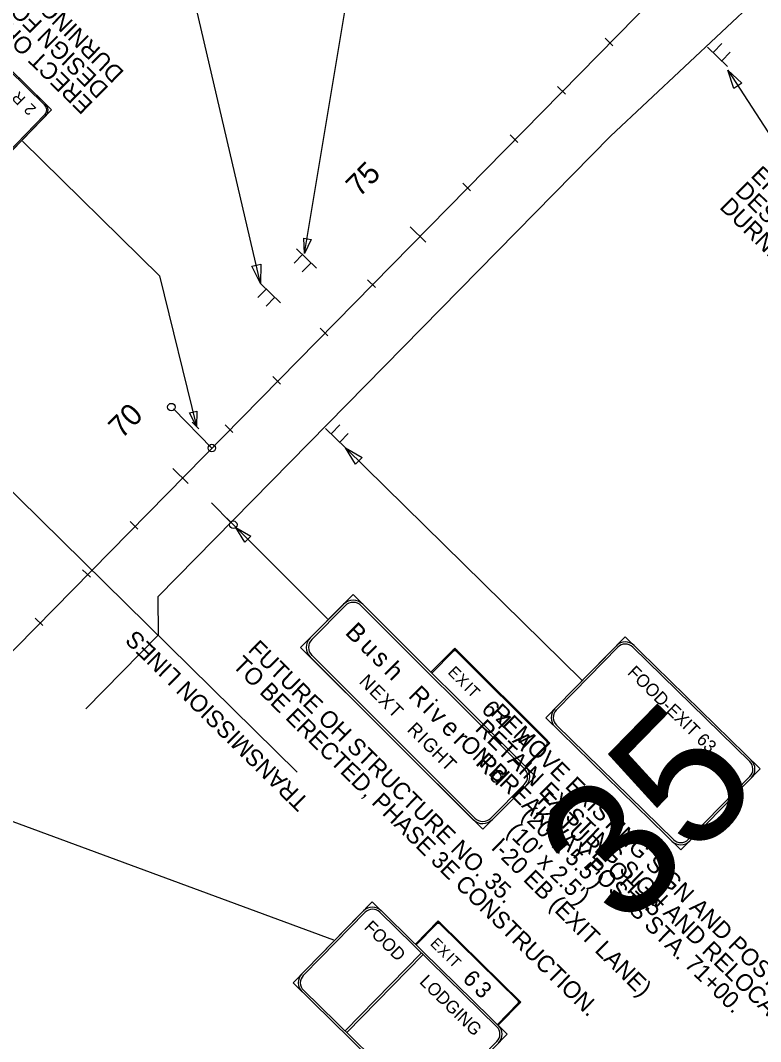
# Model space of a CAD drawing. Extents: x -5665 to 1997148, y 4 to 812485.
# Drawn here: x 1959336 to 1960429, y 795278 to 796785 of the extents above; entities that cross this region are included whole.
import ezdxf

# ---------------------------------------------------------------- set-up
doc = ezdxf.new("R2010")
doc.units = 0
for name, color, linetype in [('Default', 7, 'Continuous'), ('RD_HC_CL_Rel', 7, 'Continuous'), ('RD_HC_Data_Tic_Rel', 7, 'Continuous'), ('RD_HC_TX_Rel_Sta50', 7, 'Continuous'), ('RD_PD_Final_TX', 7, 'Continuous'), ('RD_SHT_TX', 7, 'Continuous'), ('TR SN EXTRUDED PANEL SIGNS- MOUNTED OVERHEAD', 7, 'Continuous'), ('TR SN UNASSIGNED 10', 7, 'Continuous')]:
    doc.layers.add(name, color=color, linetype=linetype)

msp = doc.modelspace()

# ---------------------------------------------------------------- linework, layer by layer
at = {"layer": 'Default'}
for p, q in [((1960207.3, 796614.2), (1960426.3, 796819.7)), ((1959539.4, 795935.2), (1960207.3, 796614.2)), ((1959539.9, 795878.6), (1959539.4, 795935.2)), ((1959432.5, 795769.5), (1959539.9, 795878.6))]:
    msp.add_line(p, q, dxfattribs=at)
at = {"layer": 'RD_HC_CL_Rel'}
msp.add_line((1957622, 794124.4), (1963740.1, 800343.8), dxfattribs=at)
at = {"layer": 'RD_HC_Data_Tic_Rel'}
for p, q in [((1960210.9, 796747.6), (1960199.5, 796758.8)), ((1960140.7, 796676.3), (1960129.3, 796687.5)), ((1960070.6, 796605), (1960059.2, 796616.2)), ((1960000.5, 796533.7), (1959989.1, 796544.9)), ((1959934.6, 796458.2), (1959911.8, 796480.6)), ((1959860.2, 796391.1), (1959848.8, 796402.3)), ((1959790.1, 796319.8), (1959778.7, 796331)), ((1959720, 796248.5), (1959708.6, 796259.8)), ((1959649.8, 796177.2), (1959638.4, 796188.5)), ((1959584, 796101.7), (1959561.2, 796124.2)), ((1959509.6, 796034.7), (1959498.2, 796045.9)), ((1959439.5, 795963.4), (1959428, 795974.6)), ((1959369.3, 795892.1), (1959357.9, 795903.3))]:
    msp.add_line(p, q, dxfattribs=at)
at = {"layer": 'RD_PD_Final_TX'}
for points in [[(1960401.3, 796692.4), (1960389.7, 796684.9), (1960380.5, 796711.8)], [(1959677.8, 796422.5), (1959691.2, 796425.6), (1959690.8, 796397.2)], [(1959840.7, 796140.1), (1959831.1, 796130.3), (1959816.3, 796154.5)]]:
    msp.add_lwpolyline(points, close=True, dxfattribs=at)
at = {"layer": 'RD_SHT_TX'}
msp.add_line((1959283.6, 796129.4), (1959744.5, 795676), dxfattribs=at)
at = {"layer": 'TR SN EXTRUDED PANEL SIGNS- MOUNTED OVERHEAD'}
for p, q in [((1959755.5, 796441.3), (1959875.4, 797157.2)), ((1959690.8, 796397.2), (1959583.5, 796857.2)), ((1960350.6, 796745.7), (1960380.1, 796717.2)), ((1960371.7, 796751), (1960359.3, 796738.2)), ((1960383.9, 796738.3), (1960371.6, 796725.5)), ((1960380.5, 796711.8), (1960650.1, 796295.2)), ((1959541.4, 796408.1), (1959339.4, 796606.8)), ((1959740.1, 796427.1), (1959752.5, 796439.9)), ((1959773.5, 796419.6), (1959744, 796448.2)), ((1959752.3, 796414.4), (1959764.7, 796427.2)), ((1959541.4, 796408.1), (1959596, 796185.9)), ((1959720.3, 796368.7), (1959690.8, 796397.2)), ((1959686.9, 796376.1), (1959699.3, 796388.9)), ((1959699.1, 796363.4), (1959711.5, 796376.2)), ((1959618.7, 796154.2), (1959562.1, 796212)), ((1959599.5, 796182.3), (1959589.7, 796192.3)), ((1959786.7, 796183.1), (1959816.3, 796154.5)), ((1959807.9, 796188.3), (1959795.5, 796175.5)), ((1959820.1, 796175.6), (1959807.7, 796162.8)), ((1959816.3, 796154.5), (1960165, 795811.5)), ((1959275.7, 795621.4), (1959798.6, 795428.3))]:
    msp.add_line(p, q, dxfattribs=at)
for points in [[(1959382.1, 796653.2), (1959257, 796775.5), (1959169.6, 796686.2), (1959294.7, 796563.8), (1959382.1, 796653.2), (1959382.1, 796653.2), (1959382.1, 796653.2)], [(1959371.7, 796660.4), (1959264.5, 796765.3)], [(1959266, 796766.8), (1959373.2, 796661.9)], [(1959371.7, 796660.4), (1959371.7, 796660.4), (1959371.7, 796660.4)], [(1959302, 796574.2), (1959371.9, 796645.7)], [(1959373.4, 796644.2), (1959303.5, 796572.8)], [(1960350.4, 795601), (1960428.4, 795680.7), (1960229, 795875.7), (1960151, 795795.9), (1960151, 795795.9)], [(1960151, 795795.9), (1960216, 795862.4)], [(1960218.2, 795860.2), (1960153.3, 795793.8)], [(1960412.9, 795691.5), (1960240.1, 795860.5)], [(1960151, 795795.9), (1960112.1, 795756.1), (1960112.1, 795756.1)], [(1960153.3, 795793.8), (1960127.3, 795767.2)], [(1960112.1, 795756.1), (1960311.4, 795561.1), (1960350.4, 795601)], [(1960127.5, 795745.3), (1960300.3, 795576.3)], [(1960348.2, 795603.2), (1960413.1, 795669.6)], [(1960322.2, 795576.6), (1960348.2, 795603.2)], [(1959976.9, 795209.7), (1960054.9, 795289.5), (1959855.6, 795484.4), (1959777.6, 795404.7), (1959777.6, 795404.7)], [(1959777.6, 795404.7), (1959842.6, 795471.1)], [(1959844.8, 795468.9), (1959779.8, 795402.5)], [(1960039.5, 795300.2), (1959866.7, 795469.2)], [(1959954.3, 795454.9), (1959952.9, 795456.4), (1959919.3, 795422.1), (1959919.3, 795422.1)], [(1959950.7, 795451.8), (1959920.5, 795421)], [(1960070.6, 795339), (1959955.2, 795451.9)], [(1960041.6, 795302.5), (1960075.1, 795336.7), (1959956.3, 795453)], [(1959777.6, 795404.7), (1959738.6, 795364.8), (1959738.6, 795364.8)], [(1959779.8, 795402.5), (1959753.8, 795375.9)], [(1959815.4, 795294.1), (1959927.7, 795408.9)], [(1959817.9, 795291.6), (1959930.2, 795406.5)], [(1959738.6, 795364.8), (1959937.9, 795169.9), (1959976.9, 795209.7)], [(1959754.1, 795354), (1959926.8, 795185.1)], [(1960040.5, 795303.6), (1960070.7, 795334.4)], [(1959974.7, 795211.9), (1960039.7, 795278.3)]]:
    msp.add_lwpolyline(points, dxfattribs=at)
for points in [[(1959754.5, 796464), (1959765.3, 796461.8), (1959755.5, 796441.3)], [(1959585.9, 796206.2), (1959596.6, 796208.6), (1959596, 796185.9)]]:
    msp.add_lwpolyline(points, close=True, dxfattribs=at)
for centre in [(1959559, 796214.6), (1959618.7, 796154.2)]:
    msp.add_circle(centre, 5.54, dxfattribs=at)
for centre, radius, start, end in [((1959364.5, 796653), 10.4, 315.6375, 45.6377), ((1959364.5, 796653), 12.5, 315.6375, 45.6377), ((1960229.3, 795849.4), 18.6, 45.6379, 135.6375), ((1960229.3, 795849.4), 15.5, 45.6379, 135.6375), ((1960138.3, 795756.4), 18.6, 135.6375, 225.6377), ((1960138.3, 795756.4), 15.5, 135.6375, 225.6377), ((1960402.1, 795680.4), 15.5, 315.6376, 45.6379), ((1960402.1, 795680.4), 18.6, 315.6376, 45.6379), ((1960311.1, 795587.4), 18.6, 225.6377, 315.6379), ((1960311.1, 795587.4), 15.5, 225.6377, 315.6379), ((1959855.9, 795458.1), 18.6, 45.6379, 135.6375), ((1959855.9, 795458.1), 15.5, 45.6379, 135.6375), ((1959952.9, 795449.6), 4.8, 45.6379, 135.6375), ((1959952.9, 795449.6), 3.2, 45.6379, 135.6375), ((1959764.9, 795365.1), 18.6, 135.6375, 225.6377), ((1959764.9, 795365.1), 15.5, 135.6375, 225.6377), ((1960068.4, 795336.7), 3.2, 315.6376, 45.6379), ((1960068.4, 795336.7), 4.8, 315.6376, 45.6379), ((1960028.6, 795289.2), 15.5, 315.6376, 45.6379), ((1960028.6, 795289.2), 18.6, 315.6376, 45.6379)]:
    msp.add_arc(centre, radius, start, end, dxfattribs=at)
at = {"layer": 'TR SN UNASSIGNED 10'}
for p, q in [((1959618.5, 796073.1), (1959647.4, 796043.6)), ((1959640.7, 796050.6), (1959789.5, 795902.1))]:
    msp.add_line(p, q, dxfattribs=at)
msp.add_lwpolyline([(1959676.3, 796024), (1959667.6, 796015.2), (1959654.3, 796037)], close=True, dxfattribs=at)
for points in [[(1959749.8, 795860.1), (1960018.8, 795591.7), (1960096.5, 795669.6), (1959827.5, 795938), (1959749.8, 795860.1), (1959749.8, 795860.1), (1959749.8, 795860.1)], [(1959763.9, 795874.2), (1959813.4, 795923.8)], [(1959815.7, 795921.4), (1959766.3, 795871.9)], [(1959815.7, 795921.4), (1959815.7, 795921.4), (1959815.7, 795921.4)], [(1960080, 795681.3), (1959839.3, 795921.5)], [(1959841.6, 795923.8), (1960082.3, 795683.7)], [(1960082.6, 795683.4), (1960117.9, 795718.8), (1959977.6, 795858.8), (1959942.3, 795823.4), (1959942.3, 795823.4), (1959942.3, 795823.4)], [(1959942.3, 795823.4), (1959974.1, 795855.2)], [(1959975.3, 795854.1), (1959943.5, 795822.2)], [(1959975.3, 795854.1), (1959975.3, 795854.1), (1959975.3, 795854.1)], [(1960113.2, 795721.2), (1959980, 795854.1)], [(1959981.2, 795855.2), (1960114.4, 795722.4)], [(1960004.7, 795605.8), (1959764, 795846)], [(1959766.3, 795848.3), (1960007, 795608.2)], [(1959766.3, 795848.3), (1959766.3, 795848.3), (1959766.3, 795848.3)], [(1960081.4, 795684.6), (1960113.2, 795716.5)], [(1960114.4, 795715.3), (1960082.6, 795683.4)], [(1960113.2, 795721.2), (1960113.2, 795721.2), (1960113.2, 795721.2)], [(1960081.4, 795684.6), (1960081.4, 795684.6), (1960081.4, 795684.6)], [(1960080.3, 795681.1), (1960080.3, 795681.1), (1960080.3, 795681.1)], [(1960030.6, 795608.2), (1960080, 795657.8)], [(1960082.4, 795655.4), (1960032.9, 795605.9)], [(1960030.6, 795608.2), (1960030.6, 795608.2), (1960030.6, 795608.2)]]:
    msp.add_lwpolyline(points, dxfattribs=at)
msp.add_circle((1959650.5, 796041), 5.54, dxfattribs=at)
for centre, radius, start, end in [((1959827.5, 795909.7), 20, 45.0679, 135.0675), ((1959827.5, 795909.7), 16.7, 45.0679, 135.0675), ((1959778.1, 795860.1), 20, 135.0675, 225.0677), ((1959778.1, 795860.1), 16.7, 135.0675, 225.0677), ((1959977.6, 795851.7), 5, 45.0679, 135.0675), ((1959977.6, 795851.7), 3.33, 45.0679, 135.0675), ((1960110.8, 795718.8), 3.33, 315.0677, 45.0679), ((1960110.8, 795718.8), 5, 315.0677, 45.0679), ((1960068.2, 795669.5), 20, 315.0677, 45.0679), ((1960068.2, 795669.5), 16.7, 315.0677, 45.0679), ((1960018.8, 795620), 16.7, 225.0677, 315.0679), ((1960018.8, 795620), 20, 225.0677, 315.0679)]:
    msp.add_arc(centre, radius, start, end, dxfattribs=at)

# ---------------------------------------------------------------- texts
at = {"layer": 'RD_HC_TX_Rel_Sta50'}
for s, p in [('75', (1959836.5, 796523.3)), ('70', (1959485.8, 796166.8))]:
    msp.add_text(s, height=32, rotation=45.4705, dxfattribs=at).set_placement(p)
at = {"layer": 'RD_SHT_TX'}
for s, height, rotation, p in [('TRANSMISSION LINES', 25, 135.4705, (1959763.5, 795634.2)), ('35', 200, 45.6376, (1960226.9, 795440.5))]:
    msp.add_text(s, height=height, rotation=rotation, dxfattribs=at).set_placement(p)
at = {"layer": 'TR SN EXTRUDED PANEL SIGNS- MOUNTED OVERHEAD'}
for s, height, rotation, p in [('DESIGN FOR FUTURE SIGNS  TO REPLACE EXISTING', 25, 135.3323, (1959467.7, 796685.7)), ('DURNING PHASE 3E CONSTRUCTION.', 25, 135.3323, (1959490.6, 796708.9)), ('ERECT OH STRUCTURE NO. P3C_OH-7.', 25, 135.3323, (1959444.8, 796662.6)), ('R', 16.7, 135.6376, (1959345, 796670.5)), ('2', 16.7, 135.6376, (1959360.5, 796655.4)), ('FOOD-EXIT 63', 18.587, 315.6376, (1960231.3, 795821.6)), ('REMOVE EXISTING SIGN AND POSTS.', 25, 315.6376, (1960028.8, 795761.7)), ('RETAIN EXISTING SIGN AND RELOCATE', 25, 315.6376, (1960006.1, 795738.4)), ('ON BREAKWAY POSTS STA. 71+00.', 25, 315.6376, (1959983.3, 795715.2)), ('FOOD', 18.59, 315.6376, (1959842.3, 795445.6)), ('E', 16, 315.6376, (1959940, 795421.7)), ('X', 16, 315.6376, (1959950.8, 795411.1)), ('I', 16, 315.6376, (1959963.1, 795399.1)), ('T', 16, 315.6376, (1959967.7, 795394.5)), ('6', 24, 315.6376, (1959987.7, 795369.4)), ('LODGING', 18.59, 315.6376, (1959924.3, 795365.4)), ('3', 24, 315.6376, (1960004.9, 795352.6))]:
    msp.add_text(s, height=height, rotation=rotation, dxfattribs=at).set_placement(p)
at = {"layer": 'TR SN UNASSIGNED 10'}
for s, height, rotation, p in [('ERECT OH STRUCTURE NO. 36.', 25, 315.3323, (1960413, 796555)), ('DESIGN FOR FUTURE SIGNS  TO BE ADDED', 25, 315.3323, (1960390.1, 796531.9)), ('DURNING PHASE 3E CONSTRUCTION.', 25, 315.3323, (1960367.2, 796508.7)), ('B', 26.7, 315.0677, (1959814.3, 795880.5)), ('FUTURE OH STRUCTURE NO. 35.', 25, 315.4705, (1959670.8, 795855.2)), ('u', 26.7, 315.0677, (1959836.1, 795858.7)), ('TO BE ERECTED, PHASE 3E CONSTRUCTION.', 25, 315.4705, (1959648, 795832)), ('s', 26.7, 315.0677, (1959853.7, 795841.2)), ('h', 26.7, 315.0677, (1959871.6, 795823.3)), ('N', 20, 315.0677, (1959834.9, 795808.2)), ('E', 16.7, 315.0677, (1959966.1, 795822.1)), ('X', 16.7, 315.0677, (1959977.3, 795810.9)), ('E', 20, 315.0677, (1959849.8, 795793.3)), ('R', 26.7, 315.0677, (1959907.5, 795787.5)), ('I', 16.7, 315.0677, (1959989.9, 795798.3)), ('T', 16.7, 315.0677, (1959994.7, 795793.5)), ('X', 20, 315.0677, (1959863.2, 795779.9)), ('T', 20, 315.0677, (1959877.5, 795765.7)), ('i', 26.7, 315.0677, (1959928.9, 795766.2)), ('6', 25, 315.0677, (1960015.3, 795767.1)), ('v', 26.7, 315.0677, (1959937.8, 795757.3)), ('4', 25, 315.0677, (1960033, 795749.4)), ('R', 20, 315.0677, (1959905.7, 795737.5)), ('e', 26.7, 315.0677, (1959955.7, 795739.4)), ('I', 20, 315.0677, (1959920.6, 795722.7)), ('r', 26.7, 315.0677, (1959973.9, 795721.2)), ('A', 25, 315.0677, (1960061.2, 795721.3)), ('G', 20, 315.0677, (1959927.1, 795716.2)), ('H', 20, 315.0677, (1959942, 795701.3)), ('T', 20, 315.0677, (1959956.2, 795687.2)), ('R', 26.7, 315.0677, (1960006.8, 795688.4)), ('d', 26.7, 315.0677, (1960026.8, 795668.5)), ('FUTURE OH-35', 25, 315.3323, (1960097.6, 795631.9)), ("(20' x 5.5')", 25, 315.3323, (1960074.5, 795610.9)), ("(10' x 2.5')", 25, 315.3323, (1960052.5, 795586.5)), ('I-20 EB (EXIT LANE)', 25, 315.3323, (1960029.6, 795563.4))]:
    msp.add_text(s, height=height, rotation=rotation, dxfattribs=at).set_placement(p)

doc.saveas('drawing.dxf')
